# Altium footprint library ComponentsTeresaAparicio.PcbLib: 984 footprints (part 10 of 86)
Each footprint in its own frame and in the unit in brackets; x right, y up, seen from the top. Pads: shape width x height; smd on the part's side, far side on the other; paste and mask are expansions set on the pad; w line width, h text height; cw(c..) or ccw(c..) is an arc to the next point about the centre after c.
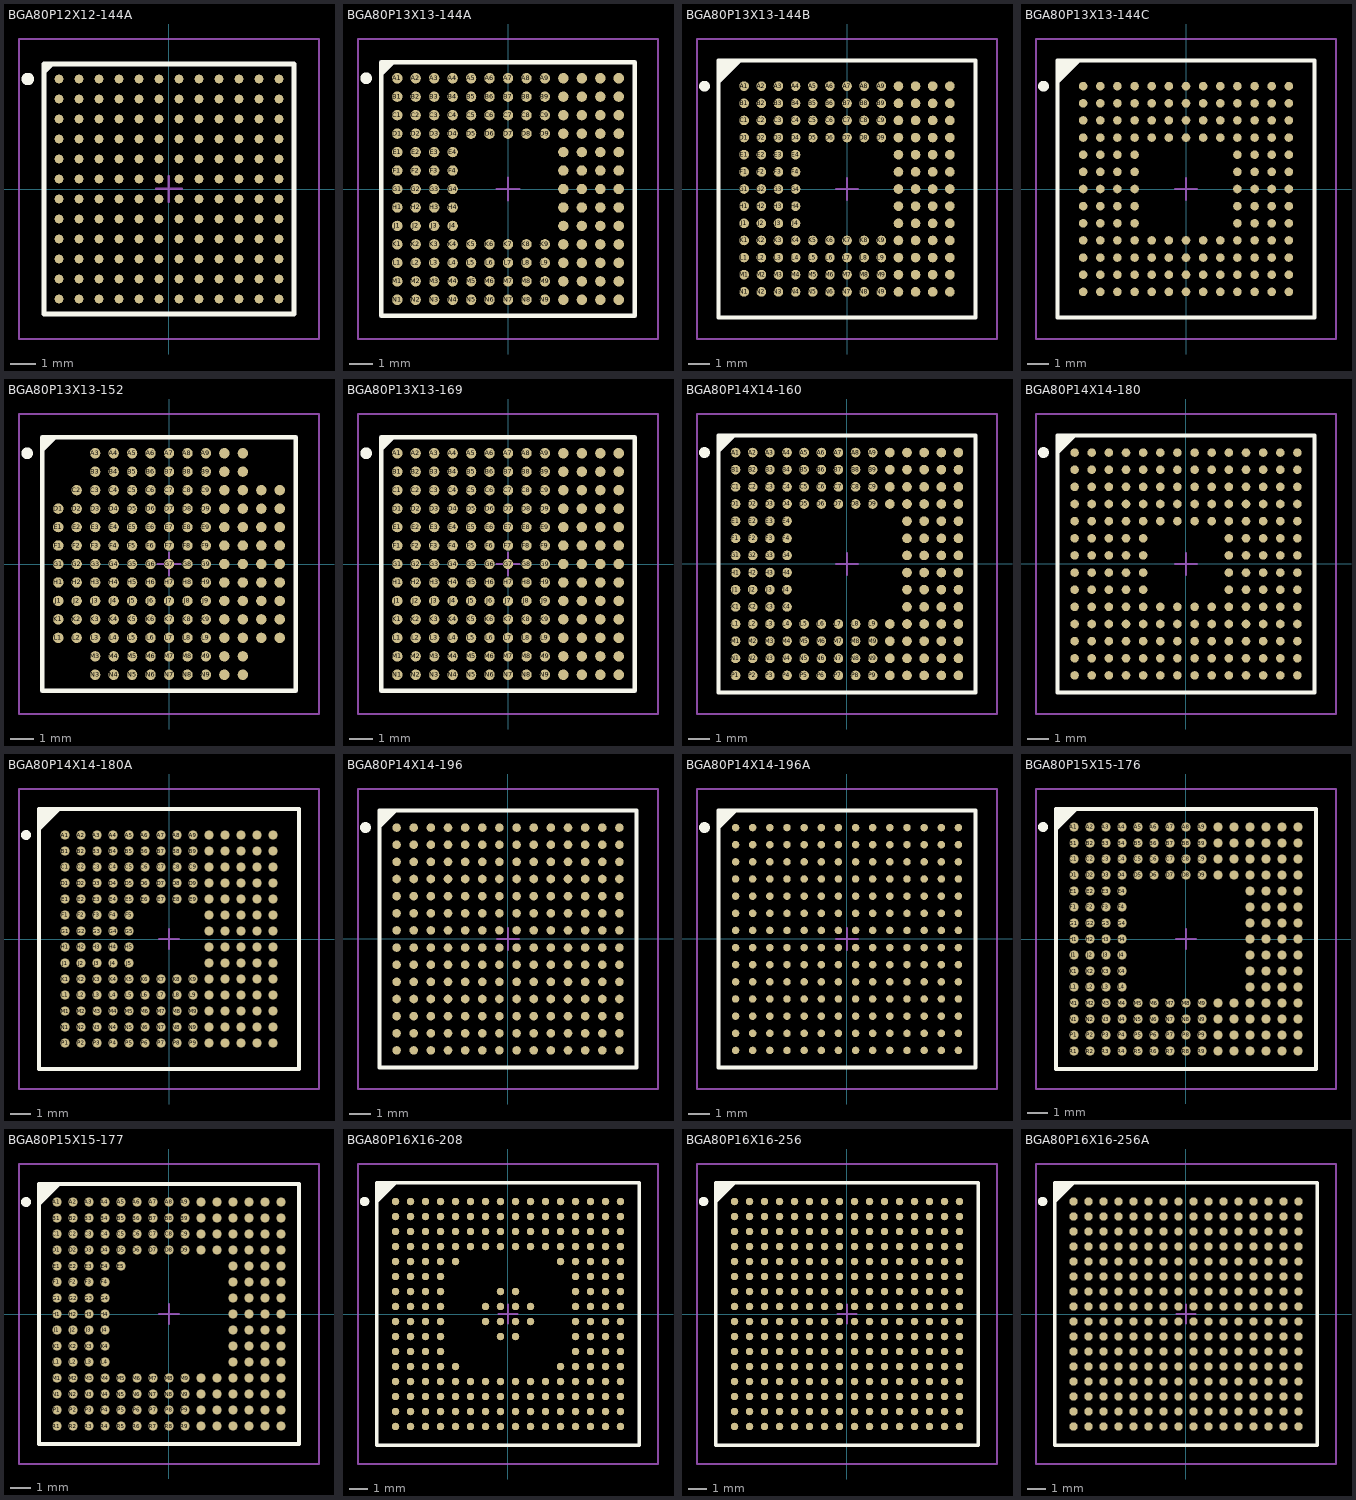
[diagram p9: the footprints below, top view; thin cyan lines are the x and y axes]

## BGA80P12X12-144A [mm] "BGA, 144-Leads, Body 10x10mm, Pitch 0.8mm"
height 1.7
pads (144):
  round 0.35 smd: A1(-4.4,4.4) A2(-3.6,4.4) A3(-2.8,4.4) A4(-2,4.4) A5(-1.2,4.4) A6(-0.4,4.4) A7(0.4,4.4) A8(1.2,4.4) A9(2,4.4) A10(2.8,4.4) A11(3.6,4.4) A12(4.4,4.4) B1(-4.4,3.6) B2(-3.6,3.6) B3(-2.8,3.6) B4(-2,3.6) B5(-1.2,3.6) B6(-0.4,3.6) B7(0.4,3.6) B8(1.2,3.6) B9(2,3.6) B10(2.8,3.6) B11(3.6,3.6) B12(4.4,3.6) C1(-4.4,2.8) C2(-3.6,2.8) C3(-2.8,2.8) C4(-2,2.8) C5(-1.2,2.8) C6(-0.4,2.8) C7(0.4,2.8) C8(1.2,2.8) C9(2,2.8) C10(2.8,2.8) C11(3.6,2.8) C12(4.4,2.8) D1(-4.4,2) D2(-3.6,2) D3(-2.8,2) D4(-2,2) D5(-1.2,2) D6(-0.4,2) D7(0.4,2) D8(1.2,2) D9(2,2) D10(2.8,2) D11(3.6,2) D12(4.4,2) E1(-4.4,1.2) E2(-3.6,1.2) E3(-2.8,1.2) E4(-2,1.2) E5(-1.2,1.2) E6(-0.4,1.2) E7(0.4,1.2) E8(1.2,1.2) E9(2,1.2) E10(2.8,1.2) E11(3.6,1.2) E12(4.4,1.2) F1(-4.4,0.4) F2(-3.6,0.4) F3(-2.8,0.4) F4(-2,0.4) F5(-1.2,0.4) F6(-0.4,0.4) F7(0.4,0.4) F8(1.2,0.4) F9(2,0.4) F10(2.8,0.4) F11(3.6,0.4) F12(4.4,0.4) G1(-4.4,-0.4) G2(-3.6,-0.4) G3(-2.8,-0.4) G4(-2,-0.4) G5(-1.2,-0.4) G6(-0.4,-0.4) G7(0.4,-0.4) G8(1.2,-0.4) G9(2,-0.4) G10(2.8,-0.4) G11(3.6,-0.4) G12(4.4,-0.4) H1(-4.4,-1.2) H2(-3.6,-1.2) H3(-2.8,-1.2) H4(-2,-1.2) H5(-1.2,-1.2) H6(-0.4,-1.2) H7(0.4,-1.2) H8(1.2,-1.2) H9(2,-1.2) H10(2.8,-1.2) H11(3.6,-1.2) H12(4.4,-1.2) J1(-4.4,-2) J2(-3.6,-2) J3(-2.8,-2) J4(-2,-2) J5(-1.2,-2) J6(-0.4,-2) J7(0.4,-2) J8(1.2,-2) J9(2,-2) J10(2.8,-2) J11(3.6,-2) J12(4.4,-2) K1(-4.4,-2.8) K2(-3.6,-2.8) K3(-2.8,-2.8) K4(-2,-2.8) K5(-1.2,-2.8) K6(-0.4,-2.8) K7(0.4,-2.8) K8(1.2,-2.8) K9(2,-2.8) K10(2.8,-2.8) K11(3.6,-2.8) K12(4.4,-2.8) L1(-4.4,-3.6) L2(-3.6,-3.6) L3(-2.8,-3.6) L4(-2,-3.6) L5(-1.2,-3.6) L6(-0.4,-3.6) L7(0.4,-3.6) L8(1.2,-3.6) L9(2,-3.6) L10(2.8,-3.6) L11(3.6,-3.6) L12(4.4,-3.6) M1(-4.4,-4.4) M2(-3.6,-4.4) M3(-2.8,-4.4) M4(-2,-4.4) M5(-1.2,-4.4) M6(-0.4,-4.4) M7(0.4,-4.4) M8(1.2,-4.4) M9(2,-4.4) M10(2.8,-4.4) M11(3.6,-4.4) M12(4.4,-4.4)
Top Overlay:
  circle w0.25: c-5.65,4.4 r0.125
  region: -4.684,5 -5,4.684 -5,5
  lines w0.2: -5,4.684 -4.684,5 ; -5,-5 -5,5 5,5 5,-5 -5,-5
Mechanical 13:
  lines w0.1: -5,-5 -5,5 5,5 5,-5 -5,-5
Mechanical 15:
  lines w0.1: -0.5,0 0.5,0 ; 0,-0.5 0,0.5 ; -6,-6 -6,6 6,6 6,-6 -6,-6
3D body: height 1.4, standoff 0, extent -5,-5 5,5

## BGA80P13X13-144A [mm] "BGA, 144-Leads, Body 11x11mm, Pitch 0.8mm"
height 1.5
pads (144):
  round 0.45 smd: A1(-4.8,4.8) A2(-4,4.8) A3(-3.2,4.8) A4(-2.4,4.8) A5(-1.6,4.8) A6(-0.8,4.8) A7(0,4.8) A8(0.8,4.8) A9(1.6,4.8) A10(2.4,4.8) A11(3.2,4.8) A12(4,4.8) A13(4.8,4.8) B1(-4.8,4) B2(-4,4) B3(-3.2,4) B4(-2.4,4) B5(-1.6,4) B6(-0.8,4) B7(0,4) B8(0.8,4) B9(1.6,4) B10(2.4,4) B11(3.2,4) B12(4,4) B13(4.8,4) C1(-4.8,3.2) C2(-4,3.2) C3(-3.2,3.2) C4(-2.4,3.2) C5(-1.6,3.2) C6(-0.8,3.2) C7(0,3.2) C8(0.8,3.2) C9(1.6,3.2) C10(2.4,3.2) C11(3.2,3.2) C12(4,3.2) C13(4.8,3.2) D1(-4.8,2.4) D2(-4,2.4) D3(-3.2,2.4) D4(-2.4,2.4) D5(-1.6,2.4) D6(-0.8,2.4) D7(0,2.4) D8(0.8,2.4) D9(1.6,2.4) D10(2.4,2.4) D11(3.2,2.4) D12(4,2.4) D13(4.8,2.4) E1(-4.8,1.6) E2(-4,1.6) E3(-3.2,1.6) E4(-2.4,1.6) E10(2.4,1.6) E11(3.2,1.6) E12(4,1.6) E13(4.8,1.6) F1(-4.8,0.8) F2(-4,0.8) F3(-3.2,0.8) F4(-2.4,0.8) F10(2.4,0.8) F11(3.2,0.8) F12(4,0.8) F13(4.8,0.8) G1(-4.8,0) G2(-4,0) G3(-3.2,0) G4(-2.4,0) G10(2.4,0) G11(3.2,0) G12(4,0) G13(4.8,0) H1(-4.8,-0.8) H2(-4,-0.8) H3(-3.2,-0.8) H4(-2.4,-0.8) H10(2.4,-0.8) H11(3.2,-0.8) H12(4,-0.8) H13(4.8,-0.8) J1(-4.8,-1.6) J2(-4,-1.6) J3(-3.2,-1.6) J4(-2.4,-1.6) J10(2.4,-1.6) J11(3.2,-1.6) J12(4,-1.6) J13(4.8,-1.6) K1(-4.8,-2.4) K2(-4,-2.4) K3(-3.2,-2.4) K4(-2.4,-2.4) K5(-1.6,-2.4) K6(-0.8,-2.4) K7(0,-2.4) K8(0.8,-2.4) K9(1.6,-2.4) K10(2.4,-2.4) K11(3.2,-2.4) K12(4,-2.4) K13(4.8,-2.4) L1(-4.8,-3.2) L2(-4,-3.2) L3(-3.2,-3.2) L4(-2.4,-3.2) L5(-1.6,-3.2) L6(-0.8,-3.2) L7(0,-3.2) L8(0.8,-3.2) L9(1.6,-3.2) L10(2.4,-3.2) L11(3.2,-3.2) L12(4,-3.2) L13(4.8,-3.2) M1(-4.8,-4) M2(-4,-4) M3(-3.2,-4) M4(-2.4,-4) M5(-1.6,-4) M6(-0.8,-4) M7(0,-4) M8(0.8,-4) M9(1.6,-4) M10(2.4,-4) M11(3.2,-4) M12(4,-4) M13(4.8,-4) N1(-4.8,-4.8) N2(-4,-4.8) N3(-3.2,-4.8) N4(-2.4,-4.8) N5(-1.6,-4.8) N6(-0.8,-4.8) N7(0,-4.8) N8(0.8,-4.8) N9(1.6,-4.8) N10(2.4,-4.8) N11(3.2,-4.8) N12(4,-4.8) N13(4.8,-4.8)
Top Overlay:
  circle w0.25: c-6.15,4.8 r0.125
  region: -4.984,5.5 -5.5,4.984 -5.5,5.5
  lines w0.2: -5.5,4.984 -4.984,5.5 ; -5.5,-5.5 5.5,-5.5 5.5,5.5 -5.5,5.5 -5.5,-5.5
Mechanical 13:
  lines w0.1: -5.5,-5.5 5.5,-5.5 5.5,5.5 -5.5,5.5 -5.5,-5.5
Mechanical 15:
  lines w0.1: -0.5,0 0.5,0 ; 0,-0.5 0,0.5 ; -6.5,-6.5 6.5,-6.5 6.5,6.5 -6.5,6.5 -6.5,-6.5
3D body: height 1.5, standoff 0, extent -5.5,-5.5 5.5,5.5

## BGA80P13X13-144B [mm] "144-Ball Ball Grid Array 0.8 mm Pitch"
height 1.4
pads (144):
  round 0.45 smd: A1(-4.8,4.8) A2(-4,4.8) A3(-3.2,4.8) A4(-2.4,4.8) A5(-1.6,4.8) A6(-0.8,4.8) A7(0,4.8) A8(0.8,4.8) A9(1.6,4.8) A10(2.4,4.8) A11(3.2,4.8) A12(4,4.8) A13(4.8,4.8) B1(-4.8,4) B2(-4,4) B3(-3.2,4) B4(-2.4,4) B5(-1.6,4) B6(-0.8,4) B7(0,4) B8(0.8,4) B9(1.6,4) B10(2.4,4) B11(3.2,4) B12(4,4) B13(4.8,4) C1(-4.8,3.2) C2(-4,3.2) C3(-3.2,3.2) C4(-2.4,3.2) C5(-1.6,3.2) C6(-0.8,3.2) C7(0,3.2) C8(0.8,3.2) C9(1.6,3.2) C10(2.4,3.2) C11(3.2,3.2) C12(4,3.2) C13(4.8,3.2) D1(-4.8,2.4) D2(-4,2.4) D3(-3.2,2.4) D4(-2.4,2.4) D5(-1.6,2.4) D6(-0.8,2.4) D7(0,2.4) D8(0.8,2.4) D9(1.6,2.4) D10(2.4,2.4) D11(3.2,2.4) D12(4,2.4) D13(4.8,2.4) E1(-4.8,1.6) E2(-4,1.6) E3(-3.2,1.6) E4(-2.4,1.6) E10(2.4,1.6) E11(3.2,1.6) E12(4,1.6) E13(4.8,1.6) F1(-4.8,0.8) F2(-4,0.8) F3(-3.2,0.8) F4(-2.4,0.8) F10(2.4,0.8) F11(3.2,0.8) F12(4,0.8) F13(4.8,0.8) G1(-4.8,0) G2(-4,0) G3(-3.2,0) G4(-2.4,0) G10(2.4,0) G11(3.2,0) G12(4,0) G13(4.8,0) H1(-4.8,-0.8) H2(-4,-0.8) H3(-3.2,-0.8) H4(-2.4,-0.8) H10(2.4,-0.8) H11(3.2,-0.8) H12(4,-0.8) H13(4.8,-0.8) J1(-4.8,-1.6) J2(-4,-1.6) J3(-3.2,-1.6) J4(-2.4,-1.6) J10(2.4,-1.6) J11(3.2,-1.6) J12(4,-1.6) J13(4.8,-1.6) K1(-4.8,-2.4) K2(-4,-2.4) K3(-3.2,-2.4) K4(-2.4,-2.4) K5(-1.6,-2.4) K6(-0.8,-2.4) K7(0,-2.4) K8(0.8,-2.4) K9(1.6,-2.4) K10(2.4,-2.4) K11(3.2,-2.4) K12(4,-2.4) K13(4.8,-2.4) L1(-4.8,-3.2) L2(-4,-3.2) L3(-3.2,-3.2) L4(-2.4,-3.2) L5(-1.6,-3.2) L6(-0.8,-3.2) L7(0,-3.2) L8(0.8,-3.2) L9(1.6,-3.2) L10(2.4,-3.2) L11(3.2,-3.2) L12(4,-3.2) L13(4.8,-3.2) M1(-4.8,-4) M2(-4,-4) M3(-3.2,-4) M4(-2.4,-4) M5(-1.6,-4) M6(-0.8,-4) M7(0,-4) M8(0.8,-4) M9(1.6,-4) M10(2.4,-4) M11(3.2,-4) M12(4,-4) M13(4.8,-4) N1(-4.8,-4.8) N2(-4,-4.8) N3(-3.2,-4.8) N4(-2.4,-4.8) N5(-1.6,-4.8) N6(-0.8,-4.8) N7(0,-4.8) N8(0.8,-4.8) N9(1.6,-4.8) N10(2.4,-4.8) N11(3.2,-4.8) N12(4,-4.8) N13(4.8,-4.8)
Top Overlay:
  circle w0.25: c-6.65,4.8 r0.125
  region: -5,6 -6,5 -6,6
  lines w0.2: -6,5 -5,6 ; -6,-6 -6,6 6,6 6,-6 -6,-6
Mechanical 13:
  lines w0.1: -6,-6 -6,6 6,6 6,-6 -6,-6
Mechanical 15:
  lines w0.1: -0.5,0 0.5,0 ; 0,-0.5 0,0.5 ; -7,-7 -7,7 7,7 7,-7 -7,-7
3D body: height 1.4, standoff 0, extent -6,-6 6,6

## BGA80P13X13-144C [mm] "144-Ball Chip Scale Ball Grid Array (CS144)"
height 1.2
pads (144):
  round 0.4 smd: A1(-4.8,4.8) A2(-4,4.8) A3(-3.2,4.8) A4(-2.4,4.8) A5(-1.6,4.8) A6(-0.8,4.8) A7(0,4.8) A8(0.8,4.8) A9(1.6,4.8) A10(2.4,4.8) A11(3.2,4.8) A12(4,4.8) A13(4.8,4.8) B1(-4.8,4) B2(-4,4) B3(-3.2,4) B4(-2.4,4) B5(-1.6,4) B6(-0.8,4) B7(0,4) B8(0.8,4) B9(1.6,4) B10(2.4,4) B11(3.2,4) B12(4,4) B13(4.8,4) C1(-4.8,3.2) C2(-4,3.2) C3(-3.2,3.2) C4(-2.4,3.2) C5(-1.6,3.2) C6(-0.8,3.2) C7(0,3.2) C8(0.8,3.2) C9(1.6,3.2) C10(2.4,3.2) C11(3.2,3.2) C12(4,3.2) C13(4.8,3.2) D1(-4.8,2.4) D2(-4,2.4) D3(-3.2,2.4) D4(-2.4,2.4) D5(-1.6,2.4) D6(-0.8,2.4) D7(0,2.4) D8(0.8,2.4) D9(1.6,2.4) D10(2.4,2.4) D11(3.2,2.4) D12(4,2.4) D13(4.8,2.4) E1(-4.8,1.6) E2(-4,1.6) E3(-3.2,1.6) E4(-2.4,1.6) E10(2.4,1.6) E11(3.2,1.6) E12(4,1.6) E13(4.8,1.6) F1(-4.8,0.8) F2(-4,0.8) F3(-3.2,0.8) F4(-2.4,0.8) F10(2.4,0.8) F11(3.2,0.8) F12(4,0.8) F13(4.8,0.8) G1(-4.8,0) G2(-4,0) G3(-3.2,0) G4(-2.4,0) G10(2.4,0) G11(3.2,0) G12(4,0) G13(4.8,0) H1(-4.8,-0.8) H2(-4,-0.8) H3(-3.2,-0.8) H4(-2.4,-0.8) H10(2.4,-0.8) H11(3.2,-0.8) H12(4,-0.8) H13(4.8,-0.8) J1(-4.8,-1.6) J2(-4,-1.6) J3(-3.2,-1.6) J4(-2.4,-1.6) J10(2.4,-1.6) J11(3.2,-1.6) J12(4,-1.6) J13(4.8,-1.6) K1(-4.8,-2.4) K2(-4,-2.4) K3(-3.2,-2.4) K4(-2.4,-2.4) K5(-1.6,-2.4) K6(-0.8,-2.4) K7(0,-2.4) K8(0.8,-2.4) K9(1.6,-2.4) K10(2.4,-2.4) K11(3.2,-2.4) K12(4,-2.4) K13(4.8,-2.4) L1(-4.8,-3.2) L2(-4,-3.2) L3(-3.2,-3.2) L4(-2.4,-3.2) L5(-1.6,-3.2) L6(-0.8,-3.2) L7(0,-3.2) L8(0.8,-3.2) L9(1.6,-3.2) L10(2.4,-3.2) L11(3.2,-3.2) L12(4,-3.2) L13(4.8,-3.2) M1(-4.8,-4) M2(-4,-4) M3(-3.2,-4) M4(-2.4,-4) M5(-1.6,-4) M6(-0.8,-4) M7(0,-4) M8(0.8,-4) M9(1.6,-4) M10(2.4,-4) M11(3.2,-4) M12(4,-4) M13(4.8,-4) N1(-4.8,-4.8) N2(-4,-4.8) N3(-3.2,-4.8) N4(-2.4,-4.8) N5(-1.6,-4.8) N6(-0.8,-4.8) N7(0,-4.8) N8(0.8,-4.8) N9(1.6,-4.8) N10(2.4,-4.8) N11(3.2,-4.8) N12(4,-4.8) N13(4.8,-4.8)
Top Overlay:
  circle w0.25: c-6.65,4.8 r0.125
  region: -5,6 -6,5 -6,6
  lines w0.2: -6,5 -5,6 ; -6,-6 -6,6 6,6 6,-6 -6,-6
Mechanical 13:
  lines w0.1: -6,-6 -6,6 6,6 6,-6 -6,-6
Mechanical 15:
  lines w0.1: -0.5,0 0.5,0 ; 0,-0.5 0,0.5 ; -7,-7 -7,7 7,7 7,-7 -7,-7
3D body: height 1.2, standoff 0, extent -6,-6 6,6

## BGA80P13X13-152 [mm] "BGA, 152-Leads, Body 11x11mm, Pitch 0.8mm"
height 1
pads (152):
  round 0.45 smd: A3(-3.2,4.8) A4(-2.4,4.8) A5(-1.6,4.8) A6(-0.8,4.8) A7(0,4.8) A8(0.8,4.8) A9(1.6,4.8) A10(2.4,4.8) A11(3.2,4.8) B3(-3.2,4) B4(-2.4,4) B5(-1.6,4) B6(-0.8,4) B7(0,4) B8(0.8,4) B9(1.6,4) B10(2.4,4) B11(3.2,4) C2(-4,3.2) C3(-3.2,3.2) C4(-2.4,3.2) C5(-1.6,3.2) C6(-0.8,3.2) C7(0,3.2) C8(0.8,3.2) C9(1.6,3.2) C10(2.4,3.2) C11(3.2,3.2) C12(4,3.2) C13(4.8,3.2) D1(-4.8,2.4) D2(-4,2.4) D3(-3.2,2.4) D4(-2.4,2.4) D5(-1.6,2.4) D6(-0.8,2.4) D7(0,2.4) D8(0.8,2.4) D9(1.6,2.4) D10(2.4,2.4) D11(3.2,2.4) D12(4,2.4) D13(4.8,2.4) E1(-4.8,1.6) E2(-4,1.6) E3(-3.2,1.6) E4(-2.4,1.6) E5(-1.6,1.6) E6(-0.8,1.6) E7(0,1.6) E8(0.8,1.6) E9(1.6,1.6) E10(2.4,1.6) E11(3.2,1.6) E12(4,1.6) E13(4.8,1.6) F1(-4.8,0.8) F2(-4,0.8) F3(-3.2,0.8) F4(-2.4,0.8) F5(-1.6,0.8) F6(-0.8,0.8) F7(0,0.8) F8(0.8,0.8) F9(1.6,0.8) F10(2.4,0.8) F11(3.2,0.8) F12(4,0.8) F13(4.8,0.8) G1(-4.8,0) G2(-4,0) G3(-3.2,0) G4(-2.4,0) G5(-1.6,0) G6(-0.8,0) G7(0,0) G8(0.8,0) G9(1.6,0) G10(2.4,0) G11(3.2,0) G12(4,0) G13(4.8,0) H1(-4.8,-0.8) H2(-4,-0.8) H3(-3.2,-0.8) H4(-2.4,-0.8) H5(-1.6,-0.8) H6(-0.8,-0.8) H7(0,-0.8) H8(0.8,-0.8) H9(1.6,-0.8) H10(2.4,-0.8) H11(3.2,-0.8) H12(4,-0.8) H13(4.8,-0.8) J1(-4.8,-1.6) J2(-4,-1.6) J3(-3.2,-1.6) J4(-2.4,-1.6) J5(-1.6,-1.6) J6(-0.8,-1.6) J7(0,-1.6) J8(0.8,-1.6) J9(1.6,-1.6) J10(2.4,-1.6) J11(3.2,-1.6) J12(4,-1.6) J13(4.8,-1.6) K1(-4.8,-2.4) K2(-4,-2.4) K3(-3.2,-2.4) K4(-2.4,-2.4) K5(-1.6,-2.4) K6(-0.8,-2.4) K7(0,-2.4) K8(0.8,-2.4) K9(1.6,-2.4) K10(2.4,-2.4) K11(3.2,-2.4) K12(4,-2.4) K13(4.8,-2.4) L1(-4.8,-3.2) L2(-4,-3.2) L3(-3.2,-3.2) L4(-2.4,-3.2) L5(-1.6,-3.2) L6(-0.8,-3.2) L7(0,-3.2) L8(0.8,-3.2) L9(1.6,-3.2) L10(2.4,-3.2) L11(3.2,-3.2) L12(4,-3.2) L13(4.8,-3.2) M3(-3.2,-4) M4(-2.4,-4) M5(-1.6,-4) M6(-0.8,-4) M7(0,-4) M8(0.8,-4) M9(1.6,-4) M10(2.4,-4) M11(3.2,-4) N3(-3.2,-4.8) N4(-2.4,-4.8) N5(-1.6,-4.8) N6(-0.8,-4.8) N7(0,-4.8) N8(0.8,-4.8) N9(1.6,-4.8) N10(2.4,-4.8) N11(3.2,-4.8)
Top Overlay:
  circle w0.25: c-6.15,4.8 r0.125
  region: -4.949,5.5 -5.5,4.949 -5.5,5.5
  lines w0.2: -5.5,4.949 -4.949,5.5 ; -5.5,-5.5 5.5,-5.5 5.5,5.5 -5.5,5.5 -5.5,-5.5
Mechanical 13:
  lines w0.1: -5.5,-5.5 5.5,-5.5 5.5,5.5 -5.5,5.5 -5.5,-5.5
Mechanical 15:
  lines w0.1: -0.5,0 0.5,0 ; 0,-0.5 0,0.5 ; -6.5,-6.5 6.5,-6.5 6.5,6.5 -6.5,6.5 -6.5,-6.5
3D body: height 1, standoff 0.05, extent -5.5,-5.5 5.5,5.5

## BGA80P13X13-169 [mm] "BGA, 169-Leads, Body 11x11mm, Pitch 0.8mm"
height 1.7
pads (169):
  round 0.45 smd: A1(-4.8,4.8) A2(-4,4.8) A3(-3.2,4.8) A4(-2.4,4.8) A5(-1.6,4.8) A6(-0.8,4.8) A7(0,4.8) A8(0.8,4.8) A9(1.6,4.8) A10(2.4,4.8) A11(3.2,4.8) A12(4,4.8) A13(4.8,4.8) B1(-4.8,4) B2(-4,4) B3(-3.2,4) B4(-2.4,4) B5(-1.6,4) B6(-0.8,4) B7(0,4) B8(0.8,4) B9(1.6,4) B10(2.4,4) B11(3.2,4) B12(4,4) B13(4.8,4) C1(-4.8,3.2) C2(-4,3.2) C3(-3.2,3.2) C4(-2.4,3.2) C5(-1.6,3.2) C6(-0.8,3.2) C7(0,3.2) C8(0.8,3.2) C9(1.6,3.2) C10(2.4,3.2) C11(3.2,3.2) C12(4,3.2) C13(4.8,3.2) D1(-4.8,2.4) D2(-4,2.4) D3(-3.2,2.4) D4(-2.4,2.4) D5(-1.6,2.4) D6(-0.8,2.4) D7(0,2.4) D8(0.8,2.4) D9(1.6,2.4) D10(2.4,2.4) D11(3.2,2.4) D12(4,2.4) D13(4.8,2.4) E1(-4.8,1.6) E2(-4,1.6) E3(-3.2,1.6) E4(-2.4,1.6) E5(-1.6,1.6) E6(-0.8,1.6) E7(0,1.6) E8(0.8,1.6) E9(1.6,1.6) E10(2.4,1.6) E11(3.2,1.6) E12(4,1.6) E13(4.8,1.6) F1(-4.8,0.8) F2(-4,0.8) F3(-3.2,0.8) F4(-2.4,0.8) F5(-1.6,0.8) F6(-0.8,0.8) F7(0,0.8) F8(0.8,0.8) F9(1.6,0.8) F10(2.4,0.8) F11(3.2,0.8) F12(4,0.8) F13(4.8,0.8) G1(-4.8,0) G2(-4,0) G3(-3.2,0) G4(-2.4,0) G5(-1.6,0) G6(-0.8,0) G7(0,0) G8(0.8,0) G9(1.6,0) G10(2.4,0) G11(3.2,0) G12(4,0) G13(4.8,0) H1(-4.8,-0.8) H2(-4,-0.8) H3(-3.2,-0.8) H4(-2.4,-0.8) H5(-1.6,-0.8) H6(-0.8,-0.8) H7(0,-0.8) H8(0.8,-0.8) H9(1.6,-0.8) H10(2.4,-0.8) H11(3.2,-0.8) H12(4,-0.8) H13(4.8,-0.8) J1(-4.8,-1.6) J2(-4,-1.6) J3(-3.2,-1.6) J4(-2.4,-1.6) J5(-1.6,-1.6) J6(-0.8,-1.6) J7(0,-1.6) J8(0.8,-1.6) J9(1.6,-1.6) J10(2.4,-1.6) J11(3.2,-1.6) J12(4,-1.6) J13(4.8,-1.6) K1(-4.8,-2.4) K2(-4,-2.4) K3(-3.2,-2.4) K4(-2.4,-2.4) K5(-1.6,-2.4) K6(-0.8,-2.4) K7(0,-2.4) K8(0.8,-2.4) K9(1.6,-2.4) K10(2.4,-2.4) K11(3.2,-2.4) K12(4,-2.4) K13(4.8,-2.4) L1(-4.8,-3.2) L2(-4,-3.2) L3(-3.2,-3.2) L4(-2.4,-3.2) L5(-1.6,-3.2) L6(-0.8,-3.2) L7(0,-3.2) L8(0.8,-3.2) L9(1.6,-3.2) L10(2.4,-3.2) L11(3.2,-3.2) L12(4,-3.2) L13(4.8,-3.2) M1(-4.8,-4) M2(-4,-4) M3(-3.2,-4) M4(-2.4,-4) M5(-1.6,-4) M6(-0.8,-4) M7(0,-4) M8(0.8,-4) M9(1.6,-4) M10(2.4,-4) M11(3.2,-4) M12(4,-4) M13(4.8,-4) N1(-4.8,-4.8) N2(-4,-4.8) N3(-3.2,-4.8) N4(-2.4,-4.8) N5(-1.6,-4.8) N6(-0.8,-4.8) N7(0,-4.8) N8(0.8,-4.8) N9(1.6,-4.8) N10(2.4,-4.8) N11(3.2,-4.8) N12(4,-4.8) N13(4.8,-4.8)
Top Overlay:
  circle w0.25: c-6.15,4.8 r0.125
  region: -4.984,5.5 -5.5,4.984 -5.5,5.5
  lines w0.2: -5.5,4.984 -4.984,5.5 ; -5.5,-5.5 -5.5,5.5 5.5,5.5 5.5,-5.5 -5.5,-5.5
Mechanical 13:
  lines w0.1: -5.5,-5.5 -5.5,5.5 5.5,5.5 5.5,-5.5 -5.5,-5.5
Mechanical 15:
  lines w0.1: -0.5,0 0.5,0 ; 0,-0.5 0,0.5 ; -6.5,-6.5 -6.5,6.5 6.5,6.5 6.5,-6.5 -6.5,-6.5
3D body: height 1.7, standoff 0, extent -5.5,-5.5 5.5,5.5

## BGA80P14X14-160 [mm] "BGA, 160-Leads, Body 12x12mm, Pitch 0.8mm"
height 1.7
pads (160):
  round 0.45 smd: A1(-5.2,5.2) A2(-4.4,5.2) A3(-3.6,5.2) A4(-2.8,5.2) A5(-2,5.2) A6(-1.2,5.2) A7(-0.4,5.2) A8(0.4,5.2) A9(1.2,5.2) A10(2,5.2) A11(2.8,5.2) A12(3.6,5.2) A13(4.4,5.2) A14(5.2,5.2) B1(-5.2,4.4) B2(-4.4,4.4) B3(-3.6,4.4) B4(-2.8,4.4) B5(-2,4.4) B6(-1.2,4.4) B7(-0.4,4.4) B8(0.4,4.4) B9(1.2,4.4) B10(2,4.4) B11(2.8,4.4) B12(3.6,4.4) B13(4.4,4.4) B14(5.2,4.4) C1(-5.2,3.6) C2(-4.4,3.6) C3(-3.6,3.6) C4(-2.8,3.6) C5(-2,3.6) C6(-1.2,3.6) C7(-0.4,3.6) C8(0.4,3.6) C9(1.2,3.6) C10(2,3.6) C11(2.8,3.6) C12(3.6,3.6) C13(4.4,3.6) C14(5.2,3.6) D1(-5.2,2.8) D2(-4.4,2.8) D3(-3.6,2.8) D4(-2.8,2.8) D5(-2,2.8) D6(-1.2,2.8) D7(-0.4,2.8) D8(0.4,2.8) D9(1.2,2.8) D10(2,2.8) D11(2.8,2.8) D12(3.6,2.8) D13(4.4,2.8) D14(5.2,2.8) E1(-5.2,2) E2(-4.4,2) E3(-3.6,2) E4(-2.8,2) E11(2.8,2) E12(3.6,2) E13(4.4,2) E14(5.2,2) F1(-5.2,1.2) F2(-4.4,1.2) F3(-3.6,1.2) F4(-2.8,1.2) F11(2.8,1.2) F12(3.6,1.2) F13(4.4,1.2) F14(5.2,1.2) G1(-5.2,0.4) G2(-4.4,0.4) G3(-3.6,0.4) G4(-2.8,0.4) G11(2.8,0.4) G12(3.6,0.4) G13(4.4,0.4) G14(5.2,0.4) H1(-5.2,-0.4) H2(-4.4,-0.4) H3(-3.6,-0.4) H4(-2.8,-0.4) H11(2.8,-0.4) H12(3.6,-0.4) H13(4.4,-0.4) H14(5.2,-0.4) J1(-5.2,-1.2) J2(-4.4,-1.2) J3(-3.6,-1.2) J4(-2.8,-1.2) J11(2.8,-1.2) J12(3.6,-1.2) J13(4.4,-1.2) J14(5.2,-1.2) K1(-5.2,-2) K2(-4.4,-2) K3(-3.6,-2) K4(-2.8,-2) K11(2.8,-2) K12(3.6,-2) K13(4.4,-2) K14(5.2,-2) L1(-5.2,-2.8) L2(-4.4,-2.8) L3(-3.6,-2.8) L4(-2.8,-2.8) L5(-2,-2.8) L6(-1.2,-2.8) L7(-0.4,-2.8) L8(0.4,-2.8) L9(1.2,-2.8) L10(2,-2.8) L11(2.8,-2.8) L12(3.6,-2.8) L13(4.4,-2.8) L14(5.2,-2.8) M1(-5.2,-3.6) M2(-4.4,-3.6) M3(-3.6,-3.6) M4(-2.8,-3.6) M5(-2,-3.6) M6(-1.2,-3.6) M7(-0.4,-3.6) M8(0.4,-3.6) M9(1.2,-3.6) M10(2,-3.6) M11(2.8,-3.6) M12(3.6,-3.6) M13(4.4,-3.6) M14(5.2,-3.6) N1(-5.2,-4.4) N2(-4.4,-4.4) N3(-3.6,-4.4) N4(-2.8,-4.4) N5(-2,-4.4) N6(-1.2,-4.4) N7(-0.4,-4.4) N8(0.4,-4.4) N9(1.2,-4.4) N10(2,-4.4) N11(2.8,-4.4) N12(3.6,-4.4) N13(4.4,-4.4) N14(5.2,-4.4) P1(-5.2,-5.2) P2(-4.4,-5.2) P3(-3.6,-5.2) P4(-2.8,-5.2) P5(-2,-5.2) P6(-1.2,-5.2) P7(-0.4,-5.2) P8(0.4,-5.2) P9(1.2,-5.2) P10(2,-5.2) P11(2.8,-5.2) P12(3.6,-5.2) P13(4.4,-5.2) P14(5.2,-5.2)
Top Overlay:
  circle w0.25: c-6.65,5.2 r0.125
  region: -5.284,6 -6,5.284 -6,6
  lines w0.2: -6,5.284 -5.284,6 ; -6,-6 -6,6 6,6 6,-6 -6,-6
Mechanical 13:
  lines w0.1: -6,-6 -6,6 6,6 6,-6 -6,-6
Mechanical 15:
  lines w0.1: -0.5,0 0.5,0 ; 0,-0.5 0,0.5 ; -7,-7 -7,7 7,7 7,-7 -7,-7
3D body: height 1.7, standoff 0, extent -6,-6 6,6

## BGA80P14X14-180 [mm] "BGA, 180-Leads, Body 12x12mm, Pitch 0.8mm"
height 1.2
pads (180):
  round 0.4 smd: A1(-5.2,5.2) A2(-4.4,5.2) A3(-3.6,5.2) A4(-2.8,5.2) A5(-2,5.2) A6(-1.2,5.2) A7(-0.4,5.2) A8(0.4,5.2) A9(1.2,5.2) A10(2,5.2) A11(2.8,5.2) A12(3.6,5.2) A13(4.4,5.2) A14(5.2,5.2) B1(-5.2,4.4) B2(-4.4,4.4) B3(-3.6,4.4) B4(-2.8,4.4) B5(-2,4.4) B6(-1.2,4.4) B7(-0.4,4.4) B8(0.4,4.4) B9(1.2,4.4) B10(2,4.4) B11(2.8,4.4) B12(3.6,4.4) B13(4.4,4.4) B14(5.2,4.4) C1(-5.2,3.6) C2(-4.4,3.6) C3(-3.6,3.6) C4(-2.8,3.6) C5(-2,3.6) C6(-1.2,3.6) C7(-0.4,3.6) C8(0.4,3.6) C9(1.2,3.6) C10(2,3.6) C11(2.8,3.6) C12(3.6,3.6) C13(4.4,3.6) C14(5.2,3.6) D1(-5.2,2.8) D2(-4.4,2.8) D3(-3.6,2.8) D4(-2.8,2.8) D5(-2,2.8) D6(-1.2,2.8) D7(-0.4,2.8) D8(0.4,2.8) D9(1.2,2.8) D10(2,2.8) D11(2.8,2.8) D12(3.6,2.8) D13(4.4,2.8) D14(5.2,2.8) E1(-5.2,2) E2(-4.4,2) E3(-3.6,2) E4(-2.8,2) E5(-2,2) E6(-1.2,2) E7(-0.4,2) E8(0.4,2) E9(1.2,2) E10(2,2) E11(2.8,2) E12(3.6,2) E13(4.4,2) E14(5.2,2) F1(-5.2,1.2) F2(-4.4,1.2) F3(-3.6,1.2) F4(-2.8,1.2) F5(-2,1.2) F10(2,1.2) F11(2.8,1.2) F12(3.6,1.2) F13(4.4,1.2) F14(5.2,1.2) G1(-5.2,0.4) G2(-4.4,0.4) G3(-3.6,0.4) G4(-2.8,0.4) G5(-2,0.4) G10(2,0.4) G11(2.8,0.4) G12(3.6,0.4) G13(4.4,0.4) G14(5.2,0.4) H1(-5.2,-0.4) H2(-4.4,-0.4) H3(-3.6,-0.4) H4(-2.8,-0.4) H5(-2,-0.4) H10(2,-0.4) H11(2.8,-0.4) H12(3.6,-0.4) H13(4.4,-0.4) H14(5.2,-0.4) J1(-5.2,-1.2) J2(-4.4,-1.2) J3(-3.6,-1.2) J4(-2.8,-1.2) J5(-2,-1.2) J10(2,-1.2) J11(2.8,-1.2) J12(3.6,-1.2) J13(4.4,-1.2) J14(5.2,-1.2) K1(-5.2,-2) K2(-4.4,-2) K3(-3.6,-2) K4(-2.8,-2) K5(-2,-2) K6(-1.2,-2) K7(-0.4,-2) K8(0.4,-2) K9(1.2,-2) K10(2,-2) K11(2.8,-2) K12(3.6,-2) K13(4.4,-2) K14(5.2,-2) L1(-5.2,-2.8) L2(-4.4,-2.8) L3(-3.6,-2.8) L4(-2.8,-2.8) L5(-2,-2.8) L6(-1.2,-2.8) L7(-0.4,-2.8) L8(0.4,-2.8) L9(1.2,-2.8) L10(2,-2.8) L11(2.8,-2.8) L12(3.6,-2.8) L13(4.4,-2.8) L14(5.2,-2.8) M1(-5.2,-3.6) M2(-4.4,-3.6) M3(-3.6,-3.6) M4(-2.8,-3.6) M5(-2,-3.6) M6(-1.2,-3.6) M7(-0.4,-3.6) M8(0.4,-3.6) M9(1.2,-3.6) M10(2,-3.6) M11(2.8,-3.6) M12(3.6,-3.6) M13(4.4,-3.6) M14(5.2,-3.6) N1(-5.2,-4.4) N2(-4.4,-4.4) N3(-3.6,-4.4) N4(-2.8,-4.4) N5(-2,-4.4) N6(-1.2,-4.4) N7(-0.4,-4.4) N8(0.4,-4.4) N9(1.2,-4.4) N10(2,-4.4) N11(2.8,-4.4) N12(3.6,-4.4) N13(4.4,-4.4) N14(5.2,-4.4) P1(-5.2,-5.2) P2(-4.4,-5.2) P3(-3.6,-5.2) P4(-2.8,-5.2) P5(-2,-5.2) P6(-1.2,-5.2) P7(-0.4,-5.2) P8(0.4,-5.2) P9(1.2,-5.2) P10(2,-5.2) P11(2.8,-5.2) P12(3.6,-5.2) P13(4.4,-5.2) P14(5.2,-5.2)
Top Overlay:
  circle w0.25: c-6.65,5.2 r0.125
  region: -5.213,6 -6,5.213 -6,6
  lines w0.2: -6,5.213 -5.213,6 ; -6,-6 6,-6 6,6 -6,6 -6,-6
Mechanical 13:
  lines w0.1: -6,-6 6,-6 6,6 -6,6 -6,-6
Mechanical 15:
  lines w0.1: -0.5,0 0.5,0 ; 0,-0.5 0,0.5 ; -7,-7 7,-7 7,7 -7,7 -7,-7
3D body: height 1.2, standoff 0, extent -5.999,-5.999 5.999,5.999

## BGA80P14X14-180A [mm] "BGA, 180-Leads, Body 13x13mm, Pitch 0.8mm"
height 1.5
pads (180):
  round 0.45 smd: A1(-5.2,5.2) A2(-4.4,5.2) A3(-3.6,5.2) A4(-2.8,5.2) A5(-2,5.2) A6(-1.2,5.2) A7(-0.4,5.2) A8(0.4,5.2) A9(1.2,5.2) A10(2,5.2) A11(2.8,5.2) A12(3.6,5.2) A13(4.4,5.2) A14(5.2,5.2) B1(-5.2,4.4) B2(-4.4,4.4) B3(-3.6,4.4) B4(-2.8,4.4) B5(-2,4.4) B6(-1.2,4.4) B7(-0.4,4.4) B8(0.4,4.4) B9(1.2,4.4) B10(2,4.4) B11(2.8,4.4) B12(3.6,4.4) B13(4.4,4.4) B14(5.2,4.4) C1(-5.2,3.6) C2(-4.4,3.6) C3(-3.6,3.6) C4(-2.8,3.6) C5(-2,3.6) C6(-1.2,3.6) C7(-0.4,3.6) C8(0.4,3.6) C9(1.2,3.6) C10(2,3.6) C11(2.8,3.6) C12(3.6,3.6) C13(4.4,3.6) C14(5.2,3.6) D1(-5.2,2.8) D2(-4.4,2.8) D3(-3.6,2.8) D4(-2.8,2.8) D5(-2,2.8) D6(-1.2,2.8) D7(-0.4,2.8) D8(0.4,2.8) D9(1.2,2.8) D10(2,2.8) D11(2.8,2.8) D12(3.6,2.8) D13(4.4,2.8) D14(5.2,2.8) E1(-5.2,2) E2(-4.4,2) E3(-3.6,2) E4(-2.8,2) E5(-2,2) E6(-1.2,2) E7(-0.4,2) E8(0.4,2) E9(1.2,2) E10(2,2) E11(2.8,2) E12(3.6,2) E13(4.4,2) E14(5.2,2) F1(-5.2,1.2) F2(-4.4,1.2) F3(-3.6,1.2) F4(-2.8,1.2) F5(-2,1.2) F10(2,1.2) F11(2.8,1.2) F12(3.6,1.2) F13(4.4,1.2) F14(5.2,1.2) G1(-5.2,0.4) G2(-4.4,0.4) G3(-3.6,0.4) G4(-2.8,0.4) G5(-2,0.4) G10(2,0.4) G11(2.8,0.4) G12(3.6,0.4) G13(4.4,0.4) G14(5.2,0.4) H1(-5.2,-0.4) H2(-4.4,-0.4) H3(-3.6,-0.4) H4(-2.8,-0.4) H5(-2,-0.4) H10(2,-0.4) H11(2.8,-0.4) H12(3.6,-0.4) H13(4.4,-0.4) H14(5.2,-0.4) J1(-5.2,-1.2) J2(-4.4,-1.2) J3(-3.6,-1.2) J4(-2.8,-1.2) J5(-2,-1.2) J10(2,-1.2) J11(2.8,-1.2) J12(3.6,-1.2) J13(4.4,-1.2) J14(5.2,-1.2) K1(-5.2,-2) K2(-4.4,-2) K3(-3.6,-2) K4(-2.8,-2) K5(-2,-2) K6(-1.2,-2) K7(-0.4,-2) K8(0.4,-2) K9(1.2,-2) K10(2,-2) K11(2.8,-2) K12(3.6,-2) K13(4.4,-2) K14(5.2,-2) L1(-5.2,-2.8) L2(-4.4,-2.8) L3(-3.6,-2.8) L4(-2.8,-2.8) L5(-2,-2.8) L6(-1.2,-2.8) L7(-0.4,-2.8) L8(0.4,-2.8) L9(1.2,-2.8) L10(2,-2.8) L11(2.8,-2.8) L12(3.6,-2.8) L13(4.4,-2.8) L14(5.2,-2.8) M1(-5.2,-3.6) M2(-4.4,-3.6) M3(-3.6,-3.6) M4(-2.8,-3.6) M5(-2,-3.6) M6(-1.2,-3.6) M7(-0.4,-3.6) M8(0.4,-3.6) M9(1.2,-3.6) M10(2,-3.6) M11(2.8,-3.6) M12(3.6,-3.6) M13(4.4,-3.6) M14(5.2,-3.6) N1(-5.2,-4.4) N2(-4.4,-4.4) N3(-3.6,-4.4) N4(-2.8,-4.4) N5(-2,-4.4) N6(-1.2,-4.4) N7(-0.4,-4.4) N8(0.4,-4.4) N9(1.2,-4.4) N10(2,-4.4) N11(2.8,-4.4) N12(3.6,-4.4) N13(4.4,-4.4) N14(5.2,-4.4) P1(-5.2,-5.2) P2(-4.4,-5.2) P3(-3.6,-5.2) P4(-2.8,-5.2) P5(-2,-5.2) P6(-1.2,-5.2) P7(-0.4,-5.2) P8(0.4,-5.2) P9(1.2,-5.2) P10(2,-5.2) P11(2.8,-5.2) P12(3.6,-5.2) P13(4.4,-5.2) P14(5.2,-5.2)
Top Overlay:
  circle w0.25: c-7.15,5.2 r0.125
  region: -5.5,6.5 -6.5,5.5 -6.5,6.5
  lines w0.2: -6.5,5.5 -5.5,6.5 ; -6.5,-6.5 -6.5,6.5 6.5,6.5 6.5,-6.5 -6.5,-6.5
Mechanical 13:
  lines w0.1: -6.5,-6.5 -6.5,6.5 6.5,6.5 6.5,-6.5 -6.5,-6.5
Mechanical 15:
  lines w0.1: -0.5,0 0.5,0 ; 0,-0.5 0,0.5 ; -7.5,-7.5 -7.5,7.5 7.5,7.5 7.5,-7.5 -7.5,-7.5
3D body: height 1.5, standoff 0, extent -6.5,-6.5 6.5,6.5

## BGA80P14X14-196 [mm] "BGA, 196-Leads, Body 12x12mm, Pitch 0.8mm"
height 1.5
pads (196):
  round 0.4 smd: A1(-5.2,5.2) A2(-4.4,5.2) A3(-3.6,5.2) A4(-2.8,5.2) A5(-2,5.2) A6(-1.2,5.2) A7(-0.4,5.2) A8(0.4,5.2) A9(1.2,5.2) A10(2,5.2) A11(2.8,5.2) A12(3.6,5.2) A13(4.4,5.2) A14(5.2,5.2) B1(-5.2,4.4) B2(-4.4,4.4) B3(-3.6,4.4) B4(-2.8,4.4) B5(-2,4.4) B6(-1.2,4.4) B7(-0.4,4.4) B8(0.4,4.4) B9(1.2,4.4) B10(2,4.4) B11(2.8,4.4) B12(3.6,4.4) B13(4.4,4.4) B14(5.2,4.4) C1(-5.2,3.6) C2(-4.4,3.6) C3(-3.6,3.6) C4(-2.8,3.6) C5(-2,3.6) C6(-1.2,3.6) C7(-0.4,3.6) C8(0.4,3.6) C9(1.2,3.6) C10(2,3.6) C11(2.8,3.6) C12(3.6,3.6) C13(4.4,3.6) C14(5.2,3.6) D1(-5.2,2.8) D2(-4.4,2.8) D3(-3.6,2.8) D4(-2.8,2.8) D5(-2,2.8) D6(-1.2,2.8) D7(-0.4,2.8) D8(0.4,2.8) D9(1.2,2.8) D10(2,2.8) D11(2.8,2.8) D12(3.6,2.8) D13(4.4,2.8) D14(5.2,2.8) E1(-5.2,2) E2(-4.4,2) E3(-3.6,2) E4(-2.8,2) E5(-2,2) E6(-1.2,2) E7(-0.4,2) E8(0.4,2) E9(1.2,2) E10(2,2) E11(2.8,2) E12(3.6,2) E13(4.4,2) E14(5.2,2) F1(-5.2,1.2) F2(-4.4,1.2) F3(-3.6,1.2) F4(-2.8,1.2) F5(-2,1.2) F6(-1.2,1.2) F7(-0.4,1.2) F8(0.4,1.2) F9(1.2,1.2) F10(2,1.2) F11(2.8,1.2) F12(3.6,1.2) F13(4.4,1.2) F14(5.2,1.2) G1(-5.2,0.4) G2(-4.4,0.4) G3(-3.6,0.4) G4(-2.8,0.4) G5(-2,0.4) G6(-1.2,0.4) G7(-0.4,0.4) G8(0.4,0.4) G9(1.2,0.4) G10(2,0.4) G11(2.8,0.4) G12(3.6,0.4) G13(4.4,0.4) G14(5.2,0.4) H1(-5.2,-0.4) H2(-4.4,-0.4) H3(-3.6,-0.4) H4(-2.8,-0.4) H5(-2,-0.4) H6(-1.2,-0.4) H7(-0.4,-0.4) H8(0.4,-0.4) H9(1.2,-0.4) H10(2,-0.4) H11(2.8,-0.4) H12(3.6,-0.4) H13(4.4,-0.4) H14(5.2,-0.4) J1(-5.2,-1.2) J2(-4.4,-1.2) J3(-3.6,-1.2) J4(-2.8,-1.2) J5(-2,-1.2) J6(-1.2,-1.2) J7(-0.4,-1.2) J8(0.4,-1.2) J9(1.2,-1.2) J10(2,-1.2) J11(2.8,-1.2) J12(3.6,-1.2) J13(4.4,-1.2) J14(5.2,-1.2) K1(-5.2,-2) K2(-4.4,-2) K3(-3.6,-2) K4(-2.8,-2) K5(-2,-2) K6(-1.2,-2) K7(-0.4,-2) K8(0.4,-2) K9(1.2,-2) K10(2,-2) K11(2.8,-2) K12(3.6,-2) K13(4.4,-2) K14(5.2,-2) L1(-5.2,-2.8) L2(-4.4,-2.8) L3(-3.6,-2.8) L4(-2.8,-2.8) L5(-2,-2.8) L6(-1.2,-2.8) L7(-0.4,-2.8) L8(0.4,-2.8) L9(1.2,-2.8) L10(2,-2.8) L11(2.8,-2.8) L12(3.6,-2.8) L13(4.4,-2.8) L14(5.2,-2.8) M1(-5.2,-3.6) M2(-4.4,-3.6) M3(-3.6,-3.6) M4(-2.8,-3.6) M5(-2,-3.6) M6(-1.2,-3.6) M7(-0.4,-3.6) M8(0.4,-3.6) M9(1.2,-3.6) M10(2,-3.6) M11(2.8,-3.6) M12(3.6,-3.6) M13(4.4,-3.6) M14(5.2,-3.6) N1(-5.2,-4.4) N2(-4.4,-4.4) N3(-3.6,-4.4) N4(-2.8,-4.4) N5(-2,-4.4) N6(-1.2,-4.4) N7(-0.4,-4.4) N8(0.4,-4.4) N9(1.2,-4.4) N10(2,-4.4) N11(2.8,-4.4) N12(3.6,-4.4) N13(4.4,-4.4) N14(5.2,-4.4) P1(-5.2,-5.2) P2(-4.4,-5.2) P3(-3.6,-5.2) P4(-2.8,-5.2) P5(-2,-5.2) P6(-1.2,-5.2) P7(-0.4,-5.2) P8(0.4,-5.2) P9(1.2,-5.2) P10(2,-5.2) P11(2.8,-5.2) P12(3.6,-5.2) P13(4.4,-5.2) P14(5.2,-5.2)
Top Overlay:
  circle w0.25: c-6.65,5.2 r0.125
  region: -5.249,6 -6,5.249 -6,6
  lines w0.2: -6,5.249 -5.249,6 ; -6,-6 6,-6 6,6 -6,6 -6,-6
Mechanical 13:
  lines w0.1: -6,-6 6,-6 6,6 -6,6 -6,-6
Mechanical 15:
  lines w0.1: -0.5,0 0.5,0 ; 0,-0.5 0,0.5 ; -7,-7 7,-7 7,7 -7,7 -7,-7
3D body: height 1.5, standoff 0, extent -6,-6 6,6

## BGA80P14X14-196A [mm] "BGA, 196-Leads, Body 12x12mm, Pitch 0.8mm"
height 1.36
pads (196):
  round 0.35 smd: A1(-5.2,5.2) A2(-4.4,5.2) A3(-3.6,5.2) A4(-2.8,5.2) A5(-2,5.2) A6(-1.2,5.2) A7(-0.4,5.2) A8(0.4,5.2) A9(1.2,5.2) A10(2,5.2) A11(2.8,5.2) A12(3.6,5.2) A13(4.4,5.2) A14(5.2,5.2) B1(-5.2,4.4) B2(-4.4,4.4) B3(-3.6,4.4) B4(-2.8,4.4) B5(-2,4.4) B6(-1.2,4.4) B7(-0.4,4.4) B8(0.4,4.4) B9(1.2,4.4) B10(2,4.4) B11(2.8,4.4) B12(3.6,4.4) B13(4.4,4.4) B14(5.2,4.4) C1(-5.2,3.6) C2(-4.4,3.6) C3(-3.6,3.6) C4(-2.8,3.6) C5(-2,3.6) C6(-1.2,3.6) C7(-0.4,3.6) C8(0.4,3.6) C9(1.2,3.6) C10(2,3.6) C11(2.8,3.6) C12(3.6,3.6) C13(4.4,3.6) C14(5.2,3.6) D1(-5.2,2.8) D2(-4.4,2.8) D3(-3.6,2.8) D4(-2.8,2.8) D5(-2,2.8) D6(-1.2,2.8) D7(-0.4,2.8) D8(0.4,2.8) D9(1.2,2.8) D10(2,2.8) D11(2.8,2.8) D12(3.6,2.8) D13(4.4,2.8) D14(5.2,2.8) E1(-5.2,2) E2(-4.4,2) E3(-3.6,2) E4(-2.8,2) E5(-2,2) E6(-1.2,2) E7(-0.4,2) E8(0.4,2) E9(1.2,2) E10(2,2) E11(2.8,2) E12(3.6,2) E13(4.4,2) E14(5.2,2) F1(-5.2,1.2) F2(-4.4,1.2) F3(-3.6,1.2) F4(-2.8,1.2) F5(-2,1.2) F6(-1.2,1.2) F7(-0.4,1.2) F8(0.4,1.2) F9(1.2,1.2) F10(2,1.2) F11(2.8,1.2) F12(3.6,1.2) F13(4.4,1.2) F14(5.2,1.2) G1(-5.2,0.4) G2(-4.4,0.4) G3(-3.6,0.4) G4(-2.8,0.4) G5(-2,0.4) G6(-1.2,0.4) G7(-0.4,0.4) G8(0.4,0.4) G9(1.2,0.4) G10(2,0.4) G11(2.8,0.4) G12(3.6,0.4) G13(4.4,0.4) G14(5.2,0.4) H1(-5.2,-0.4) H2(-4.4,-0.4) H3(-3.6,-0.4) H4(-2.8,-0.4) H5(-2,-0.4) H6(-1.2,-0.4) H7(-0.4,-0.4) H8(0.4,-0.4) H9(1.2,-0.4) H10(2,-0.4) H11(2.8,-0.4) H12(3.6,-0.4) H13(4.4,-0.4) H14(5.2,-0.4) J1(-5.2,-1.2) J2(-4.4,-1.2) J3(-3.6,-1.2) J4(-2.8,-1.2) J5(-2,-1.2) J6(-1.2,-1.2) J7(-0.4,-1.2) J8(0.4,-1.2) J9(1.2,-1.2) J10(2,-1.2) J11(2.8,-1.2) J12(3.6,-1.2) J13(4.4,-1.2) J14(5.2,-1.2) K1(-5.2,-2) K2(-4.4,-2) K3(-3.6,-2) K4(-2.8,-2) K5(-2,-2) K6(-1.2,-2) K7(-0.4,-2) K8(0.4,-2) K9(1.2,-2) K10(2,-2) K11(2.8,-2) K12(3.6,-2) K13(4.4,-2) K14(5.2,-2) L1(-5.2,-2.8) L2(-4.4,-2.8) L3(-3.6,-2.8) L4(-2.8,-2.8) L5(-2,-2.8) L6(-1.2,-2.8) L7(-0.4,-2.8) L8(0.4,-2.8) L9(1.2,-2.8) L10(2,-2.8) L11(2.8,-2.8) L12(3.6,-2.8) L13(4.4,-2.8) L14(5.2,-2.8) M1(-5.2,-3.6) M2(-4.4,-3.6) M3(-3.6,-3.6) M4(-2.8,-3.6) M5(-2,-3.6) M6(-1.2,-3.6) M7(-0.4,-3.6) M8(0.4,-3.6) M9(1.2,-3.6) M10(2,-3.6) M11(2.8,-3.6) M12(3.6,-3.6) M13(4.4,-3.6) M14(5.2,-3.6) N1(-5.2,-4.4) N2(-4.4,-4.4) N3(-3.6,-4.4) N4(-2.8,-4.4) N5(-2,-4.4) N6(-1.2,-4.4) N7(-0.4,-4.4) N8(0.4,-4.4) N9(1.2,-4.4) N10(2,-4.4) N11(2.8,-4.4) N12(3.6,-4.4) N13(4.4,-4.4) N14(5.2,-4.4) P1(-5.2,-5.2) P2(-4.4,-5.2) P3(-3.6,-5.2) P4(-2.8,-5.2) P5(-2,-5.2) P6(-1.2,-5.2) P7(-0.4,-5.2) P8(0.4,-5.2) P9(1.2,-5.2) P10(2,-5.2) P11(2.8,-5.2) P12(3.6,-5.2) P13(4.4,-5.2) P14(5.2,-5.2)
Top Overlay:
  circle w0.25: c-6.65,5.2 r0.125
  region: -5.213,6 -6,5.213 -6,6
  lines w0.2: -6,5.213 -5.213,6 ; -6,-6 6,-6 6,6 -6,6 -6,-6
Mechanical 13:
  lines w0.1: -6,-6 6,-6 6,6 -6,6 -6,-6
Mechanical 15:
  lines w0.1: -0.5,0 0.5,0 ; 0,-0.5 0,0.5 ; -7,-7 7,-7 7,7 -7,7 -7,-7
3D body: height 1.36, standoff 0, extent -6,-6 6,6

## BGA80P15X15-176 [mm] "BGA, 176-Leads, Body 13x13mm, Pitch 0.8mm"
height 1.4
pads (176):
  round 0.45 smd: A1(-5.6,5.6) A2(-4.8,5.6) A3(-4,5.6) A4(-3.2,5.6) A5(-2.4,5.6) A6(-1.6,5.6) A7(-0.8,5.6) A8(0,5.6) A9(0.8,5.6) A10(1.6,5.6) A11(2.4,5.6) A12(3.2,5.6) A13(4,5.6) A14(4.8,5.6) A15(5.6,5.6) B1(-5.6,4.8) B2(-4.8,4.8) B3(-4,4.8) B4(-3.2,4.8) B5(-2.4,4.8) B6(-1.6,4.8) B7(-0.8,4.8) B8(0,4.8) B9(0.8,4.8) B10(1.6,4.8) B11(2.4,4.8) B12(3.2,4.8) B13(4,4.8) B14(4.8,4.8) B15(5.6,4.8) C1(-5.6,4) C2(-4.8,4) C3(-4,4) C4(-3.2,4) C5(-2.4,4) C6(-1.6,4) C7(-0.8,4) C8(0,4) C9(0.8,4) C10(1.6,4) C11(2.4,4) C12(3.2,4) C13(4,4) C14(4.8,4) C15(5.6,4) D1(-5.6,3.2) D2(-4.8,3.2) D3(-4,3.2) D4(-3.2,3.2) D5(-2.4,3.2) D6(-1.6,3.2) D7(-0.8,3.2) D8(0,3.2) D9(0.8,3.2) D10(1.6,3.2) D11(2.4,3.2) D12(3.2,3.2) D13(4,3.2) D14(4.8,3.2) D15(5.6,3.2) E1(-5.6,2.4) E2(-4.8,2.4) E3(-4,2.4) E4(-3.2,2.4) E12(3.2,2.4) E13(4,2.4) E14(4.8,2.4) E15(5.6,2.4) F1(-5.6,1.6) F2(-4.8,1.6) F3(-4,1.6) F4(-3.2,1.6) F12(3.2,1.6) F13(4,1.6) F14(4.8,1.6) F15(5.6,1.6) G1(-5.6,0.8) G2(-4.8,0.8) G3(-4,0.8) G4(-3.2,0.8) G12(3.2,0.8) G13(4,0.8) G14(4.8,0.8) G15(5.6,0.8) H1(-5.6,0) H2(-4.8,0) H3(-4,0) H4(-3.2,0) H12(3.2,0) H13(4,0) H14(4.8,0) H15(5.6,0) J1(-5.6,-0.8) J2(-4.8,-0.8) J3(-4,-0.8) J4(-3.2,-0.8) J12(3.2,-0.8) J13(4,-0.8) J14(4.8,-0.8) J15(5.6,-0.8) K1(-5.6,-1.6) K2(-4.8,-1.6) K3(-4,-1.6) K4(-3.2,-1.6) K12(3.2,-1.6) K13(4,-1.6) K14(4.8,-1.6) K15(5.6,-1.6) L1(-5.6,-2.4) L2(-4.8,-2.4) L3(-4,-2.4) L4(-3.2,-2.4) L12(3.2,-2.4) L13(4,-2.4) L14(4.8,-2.4) L15(5.6,-2.4) M1(-5.6,-3.2) M2(-4.8,-3.2) M3(-4,-3.2) M4(-3.2,-3.2) M5(-2.4,-3.2) M6(-1.6,-3.2) M7(-0.8,-3.2) M8(0,-3.2) M9(0.8,-3.2) M10(1.6,-3.2) M11(2.4,-3.2) M12(3.2,-3.2) M13(4,-3.2) M14(4.8,-3.2) M15(5.6,-3.2) N1(-5.6,-4) N2(-4.8,-4) N3(-4,-4) N4(-3.2,-4) N5(-2.4,-4) N6(-1.6,-4) N7(-0.8,-4) N8(0,-4) N9(0.8,-4) N10(1.6,-4) N11(2.4,-4) N12(3.2,-4) N13(4,-4) N14(4.8,-4) N15(5.6,-4) P1(-5.6,-4.8) P2(-4.8,-4.8) P3(-4,-4.8) P4(-3.2,-4.8) P5(-2.4,-4.8) P6(-1.6,-4.8) P7(-0.8,-4.8) P8(0,-4.8) P9(0.8,-4.8) P10(1.6,-4.8) P11(2.4,-4.8) P12(3.2,-4.8) P13(4,-4.8) P14(4.8,-4.8) P15(5.6,-4.8) R1(-5.6,-5.6) R2(-4.8,-5.6) R3(-4,-5.6) R4(-3.2,-5.6) R5(-2.4,-5.6) R6(-1.6,-5.6) R7(-0.8,-5.6) R8(0,-5.6) R9(0.8,-5.6) R10(1.6,-5.6) R11(2.4,-5.6) R12(3.2,-5.6) R13(4,-5.6) R14(4.8,-5.6) R15(5.6,-5.6)
Top Overlay:
  circle w0.25: c-7.15,5.6 r0.125
  region: -5.5,6.5 -6.5,5.5 -6.5,6.5
  lines w0.2: -6.5,5.5 -5.5,6.5 ; -6.5,-6.5 6.5,-6.5 6.5,6.5 -6.5,6.5 -6.5,-6.5
Mechanical 13:
  lines w0.1: -6.5,-6.5 6.5,-6.5 6.5,6.5 -6.5,6.5 -6.5,-6.5
Mechanical 15:
  lines w0.1: -0.5,0 0.5,0 ; 0,-0.5 0,0.5 ; -7.5,-7.5 7.5,-7.5 7.5,7.5 -7.5,7.5 -7.5,-7.5
3D body: height 1.4, standoff 0.45, extent -6.5,-6.5 6.5,6.5

## BGA80P15X15-177 [mm] "BGA, 177-Leads, Body 13x13mm, Pitch 0.8mm"
height 1.4
pads (177):
  round 0.45 smd: A1(-5.6,5.6) A2(-4.8,5.6) A3(-4,5.6) A4(-3.2,5.6) A5(-2.4,5.6) A6(-1.6,5.6) A7(-0.8,5.6) A8(0,5.6) A9(0.8,5.6) A10(1.6,5.6) A11(2.4,5.6) A12(3.2,5.6) A13(4,5.6) A14(4.8,5.6) A15(5.6,5.6) B1(-5.6,4.8) B2(-4.8,4.8) B3(-4,4.8) B4(-3.2,4.8) B5(-2.4,4.8) B6(-1.6,4.8) B7(-0.8,4.8) B8(0,4.8) B9(0.8,4.8) B10(1.6,4.8) B11(2.4,4.8) B12(3.2,4.8) B13(4,4.8) B14(4.8,4.8) B15(5.6,4.8) C1(-5.6,4) C2(-4.8,4) C3(-4,4) C4(-3.2,4) C5(-2.4,4) C6(-1.6,4) C7(-0.8,4) C8(0,4) C9(0.8,4) C10(1.6,4) C11(2.4,4) C12(3.2,4) C13(4,4) C14(4.8,4) C15(5.6,4) D1(-5.6,3.2) D2(-4.8,3.2) D3(-4,3.2) D4(-3.2,3.2) D5(-2.4,3.2) D6(-1.6,3.2) D7(-0.8,3.2) D8(0,3.2) D9(0.8,3.2) D10(1.6,3.2) D11(2.4,3.2) D12(3.2,3.2) D13(4,3.2) D14(4.8,3.2) D15(5.6,3.2) E1(-5.6,2.4) E2(-4.8,2.4) E3(-4,2.4) E4(-3.2,2.4) E5(-2.4,2.4) E12(3.2,2.4) E13(4,2.4) E14(4.8,2.4) E15(5.6,2.4) F1(-5.6,1.6) F2(-4.8,1.6) F3(-4,1.6) F4(-3.2,1.6) F12(3.2,1.6) F13(4,1.6) F14(4.8,1.6) F15(5.6,1.6) G1(-5.6,0.8) G2(-4.8,0.8) G3(-4,0.8) G4(-3.2,0.8) G12(3.2,0.8) G13(4,0.8) G14(4.8,0.8) G15(5.6,0.8) H1(-5.6,0) H2(-4.8,0) H3(-4,0) H4(-3.2,0) H12(3.2,0) H13(4,0) H14(4.8,0) H15(5.6,0) J1(-5.6,-0.8) J2(-4.8,-0.8) J3(-4,-0.8) J4(-3.2,-0.8) J12(3.2,-0.8) J13(4,-0.8) J14(4.8,-0.8) J15(5.6,-0.8) K1(-5.6,-1.6) K2(-4.8,-1.6) K3(-4,-1.6) K4(-3.2,-1.6) K12(3.2,-1.6) K13(4,-1.6) K14(4.8,-1.6) K15(5.6,-1.6) L1(-5.6,-2.4) L2(-4.8,-2.4) L3(-4,-2.4) L4(-3.2,-2.4) L12(3.2,-2.4) L13(4,-2.4) L14(4.8,-2.4) L15(5.6,-2.4) M1(-5.6,-3.2) M2(-4.8,-3.2) M3(-4,-3.2) M4(-3.2,-3.2) M5(-2.4,-3.2) M6(-1.6,-3.2) M7(-0.8,-3.2) M8(0,-3.2) M9(0.8,-3.2) M10(1.6,-3.2) M11(2.4,-3.2) M12(3.2,-3.2) M13(4,-3.2) M14(4.8,-3.2) M15(5.6,-3.2) N1(-5.6,-4) N2(-4.8,-4) N3(-4,-4) N4(-3.2,-4) N5(-2.4,-4) N6(-1.6,-4) N7(-0.8,-4) N8(0,-4) N9(0.8,-4) N10(1.6,-4) N11(2.4,-4) N12(3.2,-4) N13(4,-4) N14(4.8,-4) N15(5.6,-4) P1(-5.6,-4.8) P2(-4.8,-4.8) P3(-4,-4.8) P4(-3.2,-4.8) P5(-2.4,-4.8) P6(-1.6,-4.8) P7(-0.8,-4.8) P8(0,-4.8) P9(0.8,-4.8) P10(1.6,-4.8) P11(2.4,-4.8) P12(3.2,-4.8) P13(4,-4.8) P14(4.8,-4.8) P15(5.6,-4.8) R1(-5.6,-5.6) R2(-4.8,-5.6) R3(-4,-5.6) R4(-3.2,-5.6) R5(-2.4,-5.6) R6(-1.6,-5.6) R7(-0.8,-5.6) R8(0,-5.6) R9(0.8,-5.6) R10(1.6,-5.6) R11(2.4,-5.6) R12(3.2,-5.6) R13(4,-5.6) R14(4.8,-5.6) R15(5.6,-5.6)
Top Overlay:
  circle w0.25: c-7.15,5.6 r0.125
  region: -5.5,6.5 -6.5,5.5 -6.5,6.5
  lines w0.2: -6.5,5.5 -5.5,6.5 ; -6.5,-6.5 6.5,-6.5 6.5,6.5 -6.5,6.5 -6.5,-6.5
Mechanical 13:
  lines w0.1: -6.5,-6.5 6.5,-6.5 6.5,6.5 -6.5,6.5 -6.5,-6.5
Mechanical 15:
  lines w0.1: -0.5,0 0.5,0 ; 0,-0.5 0,0.5 ; -7.5,-7.5 7.5,-7.5 7.5,7.5 -7.5,7.5 -7.5,-7.5
3D body: height 1.4, standoff 0.45, extent -6.5,-6.5 6.5,6.5

## BGA80P16X16-208 [mm] "208-Ball Chip Array Ball Grid Array"
height 1.7
pads (208):
  round 0.4 smd: A1(-6,6) A2(-5.2,6) A3(-4.4,6) A4(-3.6,6) A5(-2.8,6) A6(-2,6) A7(-1.2,6) A8(-0.4,6) A9(0.4,6) A10(1.2,6) A11(2,6) A12(2.8,6) A13(3.6,6) A14(4.4,6) A15(5.2,6) A16(6,6) B1(-6,5.2) B2(-5.2,5.2) B3(-4.4,5.2) B4(-3.6,5.2) B5(-2.8,5.2) B6(-2,5.2) B7(-1.2,5.2) B8(-0.4,5.2) B9(0.4,5.2) B10(1.2,5.2) B11(2,5.2) B12(2.8,5.2) B13(3.6,5.2) B14(4.4,5.2) B15(5.2,5.2) B16(6,5.2) C1(-6,4.4) C2(-5.2,4.4) C3(-4.4,4.4) C4(-3.6,4.4) C5(-2.8,4.4) C6(-2,4.4) C7(-1.2,4.4) C8(-0.4,4.4) C9(0.4,4.4) C10(1.2,4.4) C11(2,4.4) C12(2.8,4.4) C13(3.6,4.4) C14(4.4,4.4) C15(5.2,4.4) C16(6,4.4) D1(-6,3.6) D2(-5.2,3.6) D3(-4.4,3.6) D4(-3.6,3.6) D5(-2.8,3.6) D6(-2,3.6) D7(-1.2,3.6) D8(-0.4,3.6) D9(0.4,3.6) D10(1.2,3.6) D11(2,3.6) D12(2.8,3.6) D13(3.6,3.6) D14(4.4,3.6) D15(5.2,3.6) D16(6,3.6) E1(-6,2.8) E2(-5.2,2.8) E3(-4.4,2.8) E4(-3.6,2.8) E5(-2.8,2.8) E12(2.8,2.8) E13(3.6,2.8) E14(4.4,2.8) E15(5.2,2.8) E16(6,2.8) F1(-6,2) F2(-5.2,2) F3(-4.4,2) F4(-3.6,2) F13(3.6,2) F14(4.4,2) F15(5.2,2) F16(6,2) G1(-6,1.2) G2(-5.2,1.2) G3(-4.4,1.2) G4(-3.6,1.2) G8(-0.4,1.2) G9(0.4,1.2) G13(3.6,1.2) G14(4.4,1.2) G15(5.2,1.2) G16(6,1.2) H1(-6,0.4) H2(-5.2,0.4) H3(-4.4,0.4) H4(-3.6,0.4) H7(-1.2,0.4) H8(-0.4,0.4) H9(0.4,0.4) H10(1.2,0.4) H13(3.6,0.4) H14(4.4,0.4) H15(5.2,0.4) H16(6,0.4) J1(-6,-0.4) J2(-5.2,-0.4) J3(-4.4,-0.4) J4(-3.6,-0.4) J7(-1.2,-0.4) J8(-0.4,-0.4) J9(0.4,-0.4) J10(1.2,-0.4) J13(3.6,-0.4) J14(4.4,-0.4) J15(5.2,-0.4) J16(6,-0.4) K1(-6,-1.2) K2(-5.2,-1.2) K3(-4.4,-1.2) K4(-3.6,-1.2) K8(-0.4,-1.2) K9(0.4,-1.2) K13(3.6,-1.2) K14(4.4,-1.2) K15(5.2,-1.2) K16(6,-1.2) L1(-6,-2) L2(-5.2,-2) L3(-4.4,-2) L4(-3.6,-2) L13(3.6,-2) L14(4.4,-2) L15(5.2,-2) L16(6,-2) M1(-6,-2.8) M2(-5.2,-2.8) M3(-4.4,-2.8) M4(-3.6,-2.8) M5(-2.8,-2.8) M12(2.8,-2.8) M13(3.6,-2.8) M14(4.4,-2.8) M15(5.2,-2.8) M16(6,-2.8) N1(-6,-3.6) N2(-5.2,-3.6) N3(-4.4,-3.6) N4(-3.6,-3.6) N5(-2.8,-3.6) N6(-2,-3.6) N7(-1.2,-3.6) N8(-0.4,-3.6) N9(0.4,-3.6) N10(1.2,-3.6) N11(2,-3.6) N12(2.8,-3.6) N13(3.6,-3.6) N14(4.4,-3.6) N15(5.2,-3.6) N16(6,-3.6) P1(-6,-4.4) P2(-5.2,-4.4) P3(-4.4,-4.4) P4(-3.6,-4.4) P5(-2.8,-4.4) P6(-2,-4.4) P7(-1.2,-4.4) P8(-0.4,-4.4) P9(0.4,-4.4) P10(1.2,-4.4) P11(2,-4.4) P12(2.8,-4.4) P13(3.6,-4.4) P14(4.4,-4.4) P15(5.2,-4.4) P16(6,-4.4) R1(-6,-5.2) R2(-5.2,-5.2) R3(-4.4,-5.2) R4(-3.6,-5.2) R5(-2.8,-5.2) R6(-2,-5.2) R7(-1.2,-5.2) R8(-0.4,-5.2) R9(0.4,-5.2) R10(1.2,-5.2) R11(2,-5.2) R12(2.8,-5.2) R13(3.6,-5.2) R14(4.4,-5.2) R15(5.2,-5.2) R16(6,-5.2) T1(-6,-6) T2(-5.2,-6) T3(-4.4,-6) T4(-3.6,-6) T5(-2.8,-6) T6(-2,-6) T7(-1.2,-6) T8(-0.4,-6) T9(0.4,-6) T10(1.2,-6) T11(2,-6) T12(2.8,-6) T13(3.6,-6) T14(4.4,-6) T15(5.2,-6) T16(6,-6)
Top Overlay:
  circle w0.25: c-7.65,6 r0.125
  region: -6,7 -7,6 -7,7
  lines w0.2: -7,6 -6,7 ; -7,-7 7,-7 7,7 -7,7 -7,-7
Mechanical 13:
  lines w0.1: -7,-7 7,-7 7,7 -7,7 -7,-7
Mechanical 15:
  lines w0.1: -0.5,0 0.5,0 ; 0,-0.5 0,0.5 ; -8,-8 8,-8 8,8 -8,8 -8,-8
3D body: height 1.7, standoff 0, extent -7,-7 7,7

## BGA80P16X16-256 [mm] "256-Ball Chip Array Ball Grid Array"
height 1.7
pads (256):
  round 0.4 smd: A1(-6,6) A2(-5.2,6) A3(-4.4,6) A4(-3.6,6) A5(-2.8,6) A6(-2,6) A7(-1.2,6) A8(-0.4,6) A9(0.4,6) A10(1.2,6) A11(2,6) A12(2.8,6) A13(3.6,6) A14(4.4,6) A15(5.2,6) A16(6,6) B1(-6,5.2) B2(-5.2,5.2) B3(-4.4,5.2) B4(-3.6,5.2) B5(-2.8,5.2) B6(-2,5.2) B7(-1.2,5.2) B8(-0.4,5.2) B9(0.4,5.2) B10(1.2,5.2) B11(2,5.2) B12(2.8,5.2) B13(3.6,5.2) B14(4.4,5.2) B15(5.2,5.2) B16(6,5.2) C1(-6,4.4) C2(-5.2,4.4) C3(-4.4,4.4) C4(-3.6,4.4) C5(-2.8,4.4) C6(-2,4.4) C7(-1.2,4.4) C8(-0.4,4.4) C9(0.4,4.4) C10(1.2,4.4) C11(2,4.4) C12(2.8,4.4) C13(3.6,4.4) C14(4.4,4.4) C15(5.2,4.4) C16(6,4.4) D1(-6,3.6) D2(-5.2,3.6) D3(-4.4,3.6) D4(-3.6,3.6) D5(-2.8,3.6) D6(-2,3.6) D7(-1.2,3.6) D8(-0.4,3.6) D9(0.4,3.6) D10(1.2,3.6) D11(2,3.6) D12(2.8,3.6) D13(3.6,3.6) D14(4.4,3.6) D15(5.2,3.6) D16(6,3.6) E1(-6,2.8) E2(-5.2,2.8) E3(-4.4,2.8) E4(-3.6,2.8) E5(-2.8,2.8) E6(-2,2.8) E7(-1.2,2.8) E8(-0.4,2.8) E9(0.4,2.8) E10(1.2,2.8) E11(2,2.8) E12(2.8,2.8) E13(3.6,2.8) E14(4.4,2.8) E15(5.2,2.8) E16(6,2.8) F1(-6,2) F2(-5.2,2) F3(-4.4,2) F4(-3.6,2) F5(-2.8,2) F6(-2,2) F7(-1.2,2) F8(-0.4,2) F9(0.4,2) F10(1.2,2) F11(2,2) F12(2.8,2) F13(3.6,2) F14(4.4,2) F15(5.2,2) F16(6,2) G1(-6,1.2) G2(-5.2,1.2) G3(-4.4,1.2) G4(-3.6,1.2) G5(-2.8,1.2) G6(-2,1.2) G7(-1.2,1.2) G8(-0.4,1.2) G9(0.4,1.2) G10(1.2,1.2) G11(2,1.2) G12(2.8,1.2) G13(3.6,1.2) G14(4.4,1.2) G15(5.2,1.2) G16(6,1.2) H1(-6,0.4) H2(-5.2,0.4) H3(-4.4,0.4) H4(-3.6,0.4) H5(-2.8,0.4) H6(-2,0.4) H7(-1.2,0.4) H8(-0.4,0.4) H9(0.4,0.4) H10(1.2,0.4) H11(2,0.4) H12(2.8,0.4) H13(3.6,0.4) H14(4.4,0.4) H15(5.2,0.4) H16(6,0.4) J1(-6,-0.4) J2(-5.2,-0.4) J3(-4.4,-0.4) J4(-3.6,-0.4) J5(-2.8,-0.4) J6(-2,-0.4) J7(-1.2,-0.4) J8(-0.4,-0.4) J9(0.4,-0.4) J10(1.2,-0.4) J11(2,-0.4) J12(2.8,-0.4) J13(3.6,-0.4) J14(4.4,-0.4) J15(5.2,-0.4) J16(6,-0.4) K1(-6,-1.2) K2(-5.2,-1.2) K3(-4.4,-1.2) K4(-3.6,-1.2) K5(-2.8,-1.2) K6(-2,-1.2) K7(-1.2,-1.2) K8(-0.4,-1.2) K9(0.4,-1.2) K10(1.2,-1.2) K11(2,-1.2) K12(2.8,-1.2) K13(3.6,-1.2) K14(4.4,-1.2) K15(5.2,-1.2) K16(6,-1.2) L1(-6,-2) L2(-5.2,-2) L3(-4.4,-2) L4(-3.6,-2) L5(-2.8,-2) L6(-2,-2) L7(-1.2,-2) L8(-0.4,-2) L9(0.4,-2) L10(1.2,-2) L11(2,-2) L12(2.8,-2) L13(3.6,-2) L14(4.4,-2) L15(5.2,-2) L16(6,-2) M1(-6,-2.8) M2(-5.2,-2.8) M3(-4.4,-2.8) M4(-3.6,-2.8) M5(-2.8,-2.8) M6(-2,-2.8) M7(-1.2,-2.8) M8(-0.4,-2.8) M9(0.4,-2.8) M10(1.2,-2.8) M11(2,-2.8) M12(2.8,-2.8) M13(3.6,-2.8) M14(4.4,-2.8) M15(5.2,-2.8) M16(6,-2.8) N1(-6,-3.6) N2(-5.2,-3.6) N3(-4.4,-3.6) N4(-3.6,-3.6) N5(-2.8,-3.6) N6(-2,-3.6) N7(-1.2,-3.6) N8(-0.4,-3.6) N9(0.4,-3.6) N10(1.2,-3.6) N11(2,-3.6) N12(2.8,-3.6) N13(3.6,-3.6) N14(4.4,-3.6) N15(5.2,-3.6) N16(6,-3.6) P1(-6,-4.4) P2(-5.2,-4.4) P3(-4.4,-4.4) P4(-3.6,-4.4) P5(-2.8,-4.4) P6(-2,-4.4) P7(-1.2,-4.4) P8(-0.4,-4.4) P9(0.4,-4.4) P10(1.2,-4.4) P11(2,-4.4) P12(2.8,-4.4) P13(3.6,-4.4) P14(4.4,-4.4) P15(5.2,-4.4) P16(6,-4.4) R1(-6,-5.2) R2(-5.2,-5.2) R3(-4.4,-5.2) R4(-3.6,-5.2) R5(-2.8,-5.2) R6(-2,-5.2) R7(-1.2,-5.2) R8(-0.4,-5.2) R9(0.4,-5.2) R10(1.2,-5.2) R11(2,-5.2) R12(2.8,-5.2) R13(3.6,-5.2) R14(4.4,-5.2) R15(5.2,-5.2) R16(6,-5.2) T1(-6,-6) T2(-5.2,-6) T3(-4.4,-6) T4(-3.6,-6) T5(-2.8,-6) T6(-2,-6) T7(-1.2,-6) T8(-0.4,-6) T9(0.4,-6) T10(1.2,-6) T11(2,-6) T12(2.8,-6) T13(3.6,-6) T14(4.4,-6) T15(5.2,-6) T16(6,-6)
Top Overlay:
  circle w0.25: c-7.65,6 r0.125
  region: -6,7 -7,6 -7,7
  lines w0.2: -7,6 -6,7 ; -7,-7 -7,7 7,7 7,-7 -7,-7
Mechanical 13:
  lines w0.1: -7,-7 -7,7 7,7 7,-7 -7,-7
Mechanical 15:
  lines w0.1: -0.5,0 0.5,0 ; 0,-0.5 0,0.5 ; -8,-8 -8,8 8,8 8,-8 -8,-8
3D body: height 1.7, standoff 0, extent -7,-7 7,7

## BGA80P16X16-256A [mm] "256-Ball Ultra FineLine Ball Grid Array (UBGA) - Wire Bond"
height 2.2
pads (256):
  round 0.45 smd: A1(-6,6) A2(-5.2,6) A3(-4.4,6) A4(-3.6,6) A5(-2.8,6) A6(-2,6) A7(-1.2,6) A8(-0.4,6) A9(0.4,6) A10(1.2,6) A11(2,6) A12(2.8,6) A13(3.6,6) A14(4.4,6) A15(5.2,6) A16(6,6) B1(-6,5.2) B2(-5.2,5.2) B3(-4.4,5.2) B4(-3.6,5.2) B5(-2.8,5.2) B6(-2,5.2) B7(-1.2,5.2) B8(-0.4,5.2) B9(0.4,5.2) B10(1.2,5.2) B11(2,5.2) B12(2.8,5.2) B13(3.6,5.2) B14(4.4,5.2) B15(5.2,5.2) B16(6,5.2) C1(-6,4.4) C2(-5.2,4.4) C3(-4.4,4.4) C4(-3.6,4.4) C5(-2.8,4.4) C6(-2,4.4) C7(-1.2,4.4) C8(-0.4,4.4) C9(0.4,4.4) C10(1.2,4.4) C11(2,4.4) C12(2.8,4.4) C13(3.6,4.4) C14(4.4,4.4) C15(5.2,4.4) C16(6,4.4) D1(-6,3.6) D2(-5.2,3.6) D3(-4.4,3.6) D4(-3.6,3.6) D5(-2.8,3.6) D6(-2,3.6) D7(-1.2,3.6) D8(-0.4,3.6) D9(0.4,3.6) D10(1.2,3.6) D11(2,3.6) D12(2.8,3.6) D13(3.6,3.6) D14(4.4,3.6) D15(5.2,3.6) D16(6,3.6) E1(-6,2.8) E2(-5.2,2.8) E3(-4.4,2.8) E4(-3.6,2.8) E5(-2.8,2.8) E6(-2,2.8) E7(-1.2,2.8) E8(-0.4,2.8) E9(0.4,2.8) E10(1.2,2.8) E11(2,2.8) E12(2.8,2.8) E13(3.6,2.8) E14(4.4,2.8) E15(5.2,2.8) E16(6,2.8) F1(-6,2) F2(-5.2,2) F3(-4.4,2) F4(-3.6,2) F5(-2.8,2) F6(-2,2) F7(-1.2,2) F8(-0.4,2) F9(0.4,2) F10(1.2,2) F11(2,2) F12(2.8,2) F13(3.6,2) F14(4.4,2) F15(5.2,2) F16(6,2) G1(-6,1.2) G2(-5.2,1.2) G3(-4.4,1.2) G4(-3.6,1.2) G5(-2.8,1.2) G6(-2,1.2) G7(-1.2,1.2) G8(-0.4,1.2) G9(0.4,1.2) G10(1.2,1.2) G11(2,1.2) G12(2.8,1.2) G13(3.6,1.2) G14(4.4,1.2) G15(5.2,1.2) G16(6,1.2) H1(-6,0.4) H2(-5.2,0.4) H3(-4.4,0.4) H4(-3.6,0.4) H5(-2.8,0.4) H6(-2,0.4) H7(-1.2,0.4) H8(-0.4,0.4) H9(0.4,0.4) H10(1.2,0.4) H11(2,0.4) H12(2.8,0.4) H13(3.6,0.4) H14(4.4,0.4) H15(5.2,0.4) H16(6,0.4) J1(-6,-0.4) J2(-5.2,-0.4) J3(-4.4,-0.4) J4(-3.6,-0.4) J5(-2.8,-0.4) J6(-2,-0.4) J7(-1.2,-0.4) J8(-0.4,-0.4) J9(0.4,-0.4) J10(1.2,-0.4) J11(2,-0.4) J12(2.8,-0.4) J13(3.6,-0.4) J14(4.4,-0.4) J15(5.2,-0.4) J16(6,-0.4) K1(-6,-1.2) K2(-5.2,-1.2) K3(-4.4,-1.2) K4(-3.6,-1.2) K5(-2.8,-1.2) K6(-2,-1.2) K7(-1.2,-1.2) K8(-0.4,-1.2) K9(0.4,-1.2) K10(1.2,-1.2) K11(2,-1.2) K12(2.8,-1.2) K13(3.6,-1.2) K14(4.4,-1.2) K15(5.2,-1.2) K16(6,-1.2) L1(-6,-2) L2(-5.2,-2) L3(-4.4,-2) L4(-3.6,-2) L5(-2.8,-2) L6(-2,-2) L7(-1.2,-2) L8(-0.4,-2) L9(0.4,-2) L10(1.2,-2) L11(2,-2) L12(2.8,-2) L13(3.6,-2) L14(4.4,-2) L15(5.2,-2) L16(6,-2) M1(-6,-2.8) M2(-5.2,-2.8) M3(-4.4,-2.8) M4(-3.6,-2.8) M5(-2.8,-2.8) M6(-2,-2.8) M7(-1.2,-2.8) M8(-0.4,-2.8) M9(0.4,-2.8) M10(1.2,-2.8) M11(2,-2.8) M12(2.8,-2.8) M13(3.6,-2.8) M14(4.4,-2.8) M15(5.2,-2.8) M16(6,-2.8) N1(-6,-3.6) N2(-5.2,-3.6) N3(-4.4,-3.6) N4(-3.6,-3.6) N5(-2.8,-3.6) N6(-2,-3.6) N7(-1.2,-3.6) N8(-0.4,-3.6) N9(0.4,-3.6) N10(1.2,-3.6) N11(2,-3.6) N12(2.8,-3.6) N13(3.6,-3.6) N14(4.4,-3.6) N15(5.2,-3.6) N16(6,-3.6) P1(-6,-4.4) P2(-5.2,-4.4) P3(-4.4,-4.4) P4(-3.6,-4.4) P5(-2.8,-4.4) P6(-2,-4.4) P7(-1.2,-4.4) P8(-0.4,-4.4) P9(0.4,-4.4) P10(1.2,-4.4) P11(2,-4.4) P12(2.8,-4.4) P13(3.6,-4.4) P14(4.4,-4.4) P15(5.2,-4.4) P16(6,-4.4) R1(-6,-5.2) R2(-5.2,-5.2) R3(-4.4,-5.2) R4(-3.6,-5.2) R5(-2.8,-5.2) R6(-2,-5.2) R7(-1.2,-5.2) R8(-0.4,-5.2) R9(0.4,-5.2) R10(1.2,-5.2) R11(2,-5.2) R12(2.8,-5.2) R13(3.6,-5.2) R14(4.4,-5.2) R15(5.2,-5.2) R16(6,-5.2) T1(-6,-6) T2(-5.2,-6) T3(-4.4,-6) T4(-3.6,-6) T5(-2.8,-6) T6(-2,-6) T7(-1.2,-6) T8(-0.4,-6) T9(0.4,-6) T10(1.2,-6) T11(2,-6) T12(2.8,-6) T13(3.6,-6) T14(4.4,-6) T15(5.2,-6) T16(6,-6)
Top Overlay:
  circle w0.25: c-7.65,6 r0.125
  region: -6,7 -7,6 -7,7
  lines w0.2: -7,6 -6,7 ; -7,-7 -7,7 7,7 7,-7 -7,-7
Mechanical 13:
  lines w0.1: -7,-7 -7,7 7,7 7,-7 -7,-7
Mechanical 15:
  lines w0.1: -0.5,0 0.5,0 ; 0,-0.5 0,0.5 ; -8,-8 -8,8 8,8 8,-8 -8,-8
3D body: height 1.7, standoff 0, extent -7,-7 7,7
